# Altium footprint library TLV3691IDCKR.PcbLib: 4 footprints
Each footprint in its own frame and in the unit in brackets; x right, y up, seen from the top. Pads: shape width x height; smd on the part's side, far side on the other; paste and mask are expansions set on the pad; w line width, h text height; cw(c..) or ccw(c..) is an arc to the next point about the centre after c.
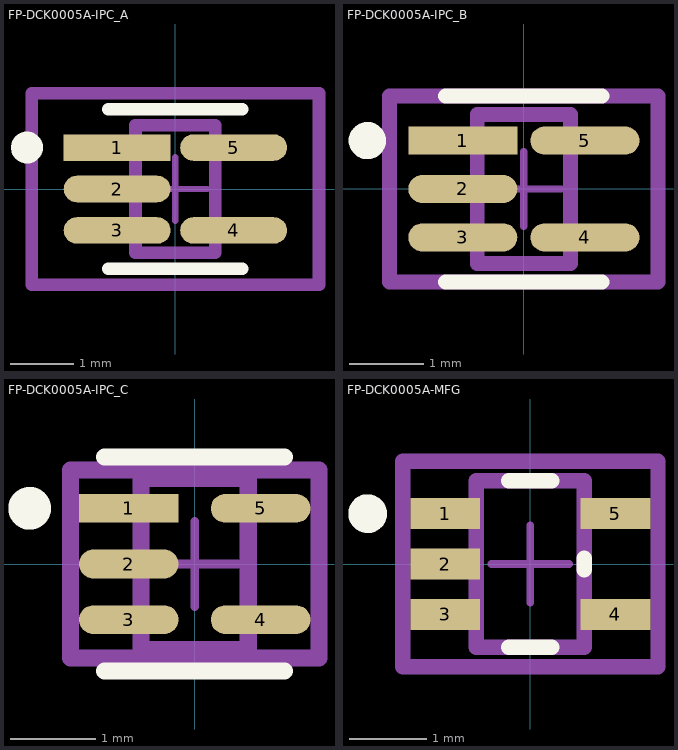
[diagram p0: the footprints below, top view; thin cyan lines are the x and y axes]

## FP-DCK0005A-IPC_A [mm]
pads (5):
  rect 1.677x0.416 smd paste+0 mask+0: 1(-0.914,0.65)
  rrect100% 1.677x0.416 smd paste+0 mask+0: 2(-0.914,0) 3(-0.914,-0.65) 4(0.914,-0.65) 5(0.914,0.65)
Top Overlay:
  circle w0.25: c-2.327,0.65 r0.125
  lines w0.2: -1.05,-1.25 1.05,-1.25 ; -1.05,1.25 1.05,1.25
Top Assembly:
  lines w0.2: -2.252,-1.5 2.252,-1.5 2.252,1.5 -2.252,1.5 -2.252,-1.5
  text ".Designator" at 0,0.188 h1
Top 3D Body:
  lines w0.2: -0.625,-1 0.625,-1 0.625,1 -0.625,1 -0.625,-1
Top Courtyard:
  lines w0.2: -2.252,-1.5 2.252,-1.5 2.252,1.5 -2.252,1.5 -2.252,-1.5
Top Component Center:
  lines w0.1: -0.5,0 0.5,0 ; 0,-0.5 0,0.5

## FP-DCK0005A-IPC_B [mm]
pads (5):
  rect 1.464x0.376 smd paste+0 mask+0: 1(-0.82,0.65)
  rrect100% 1.464x0.376 smd paste+0 mask+0: 2(-0.82,0) 3(-0.82,-0.65) 4(0.82,-0.65) 5(0.82,0.65)
Top Overlay:
  circle w0.25: c-2.102,0.65 r0.125
  lines w0.2: -1.05,-1.25 1.05,-1.25 ; -1.05,1.25 1.05,1.25
Top Assembly:
  lines w0.2: -1.802,-1.25 1.802,-1.25 1.802,1.25 -1.802,1.25 -1.802,-1.25
  text ".Designator" at 0,0.188 h1
Top 3D Body:
  lines w0.2: -0.625,-1 0.625,-1 0.625,1 -0.625,1 -0.625,-1
Top Courtyard:
  lines w0.2: -1.802,-1.25 1.802,-1.25 1.802,1.25 -1.802,1.25 -1.802,-1.25
Top Component Center:
  lines w0.1: -0.5,0 0.5,0 ; 0,-0.5 0,0.5

## FP-DCK0005A-IPC_C [mm]
pads (5):
  rect 1.164x0.336 smd paste+0 mask+0: 1(-0.77,0.65)
  rrect100% 1.164x0.336 smd paste+0 mask+0: 2(-0.77,0) 3(-0.77,-0.65) 4(0.77,-0.65) 5(0.77,0.65)
Top Overlay:
  circle w0.25: c-1.927,0.65 r0.125
  lines w0.2: -1.05,-1.25 1.05,-1.25 ; -1.05,1.25 1.05,1.25
Top Assembly:
  lines w0.2: -1.452,-1.1 1.452,-1.1 1.452,1.1 -1.452,1.1 -1.452,-1.1
  text ".Designator" at 0,0.188 h1
Top 3D Body:
  lines w0.2: -0.625,-1 0.625,-1 0.625,1 -0.625,1 -0.625,-1
Top Courtyard:
  lines w0.2: -1.452,-1.1 1.452,-1.1 1.452,1.1 -1.452,1.1 -1.452,-1.1
Top Component Center:
  lines w0.1: -0.5,0 0.5,0 ; 0,-0.5 0,0.5

## FP-DCK0005A-MFG [mm]
pads (5):
  rect 0.9x0.4 smd paste-1000 mask+0: 1(-1.1,0.65) 2(-1.1,0) 3(-1.1,-0.65) 4(1.1,-0.65) 5(1.1,0.65)
Top Overlay:
  circle w0.25: c-2.1,0.65 r0.125
  lines w0.2: -0.275,-1.075 0.275,-1.075 ; -0.275,1.075 0.275,1.075 ; 0.7,-0.075 0.7,0.075
Top Paste:
  rectangle: 0.675,-0.825 1.525,-0.475
  rectangle: 0.675,0.475 1.525,0.825
  rectangle: -1.525,-0.825 -0.675,-0.475
  rectangle: -1.525,-0.175 -0.675,0.175
  rectangle: -1.525,0.475 -0.675,0.825
Top Assembly:
  lines w0.2: -1.65,-1.325 1.65,-1.325 1.65,1.325 -1.65,1.325 -1.65,-1.325
  text ".Designator" at 0,-0.001 h1
Top 3D Body:
  lines w0.2: -0.7,-1.075 0.7,-1.075 0.7,1.075 -0.7,1.075 -0.7,-1.075
Top Courtyard:
  lines w0.2: -1.65,-1.325 1.65,-1.325 1.65,1.325 -1.65,1.325 -1.65,-1.325
Top Component Center:
  lines w0.1: -0.5,0 0.5,0 ; 0,-0.5 0,0.5
3D body "IC_Texas_Instruments_SN74AHC1G04DCKR_eec.STEP": height 0.25, standoff 0, extent -1.65,-1.325 1.65,1.325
